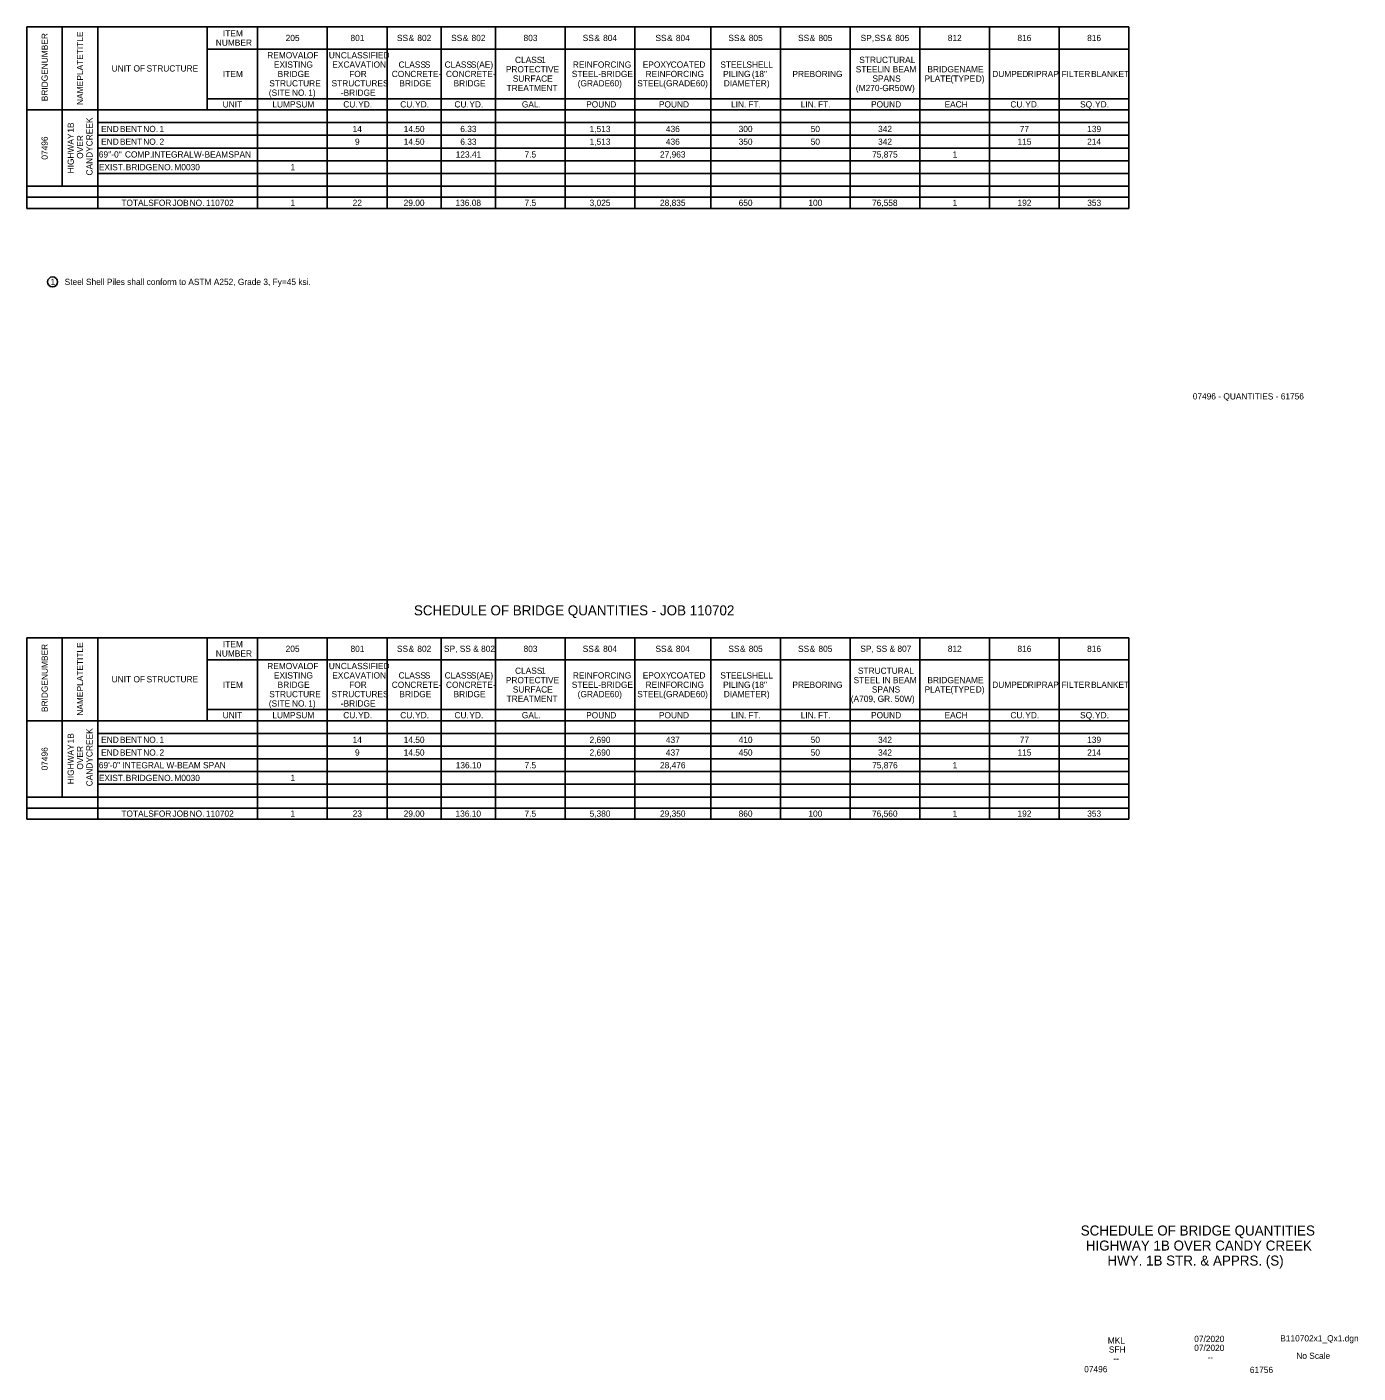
# Model space of a CAD drawing. Extents: x 305.5 to 332.2, y 135.6 to 162.6.
import ezdxf

# ---------------------------------------------------------------- set-up
doc = ezdxf.new("R2010")
doc.units = 0
for name, color, linetype in [('B_Concrete Pattern', 7, 'Continuous'), ('B_Copy In', 7, 'Continuous'), ('B_Dimensions', 7, 'Continuous'), ('B_Text', 7, 'Continuous'), ('B_Title Text', 7, 'Continuous')]:
    doc.layers.add(name, color=color, linetype=linetype)

msp = doc.modelspace()

# ---------------------------------------------------------------- linework, layer by layer
at = {"layer": 'B_Concrete Pattern'}
for p, q in [((305.498, 162.601), (305.498, 162.601)), ((305.498, 150.365), (305.498, 150.365))]:
    msp.add_line(p, q, dxfattribs=at)
at = {"layer": 'B_Dimensions'}
msp.add_circle((306.012, 157.493), 0.1, dxfattribs=at)
at = {"layer": 'B_Text'}
for p, q in [((305.498, 162.601), (327.569, 162.601)), ((305.498, 158.966), (305.498, 162.601)), ((306.207, 159.41), (306.207, 162.601)), ((306.916, 158.966), (306.916, 162.601)), ((309.11, 160.939), (309.11, 162.601)), ((310.118, 158.966), (310.118, 162.601)), ((311.514, 158.966), (311.514, 162.601)), ((312.711, 158.966), (312.711, 162.601)), ((313.797, 158.966), (313.797, 162.601)), ((314.883, 158.966), (314.883, 162.601)), ((316.279, 158.966), (316.279, 162.601)), ((317.675, 158.966), (317.675, 162.601)), ((319.193, 158.966), (319.193, 162.601)), ((320.589, 158.966), (320.589, 162.601)), ((321.985, 158.966), (321.985, 162.601)), ((323.381, 158.966), (323.381, 162.601)), ((324.777, 158.966), (324.777, 162.601)), ((326.173, 158.966), (326.173, 162.601)), ((327.569, 158.966), (327.569, 162.601)), ((309.11, 162.157), (327.569, 162.157)), ((309.11, 161.16), (327.569, 161.16)), ((305.498, 160.939), (327.569, 160.939)), ((306.916, 160.684), (327.569, 160.684)), ((306.916, 160.429), (327.569, 160.429)), ((306.916, 160.174), (327.569, 160.174)), ((306.916, 159.919), (327.569, 159.919)), ((306.916, 159.664), (327.569, 159.664)), ((305.498, 159.41), (327.569, 159.41)), ((305.498, 159.188), (327.569, 159.188)), ((305.498, 158.966), (327.569, 158.966)), ((305.498, 150.365), (327.569, 150.365)), ((305.498, 146.731), (305.498, 150.365)), ((306.207, 147.174), (306.207, 150.365)), ((306.916, 146.731), (306.916, 150.365)), ((309.11, 148.703), (309.11, 150.365)), ((310.118, 146.731), (310.118, 150.365)), ((311.514, 146.731), (311.514, 150.365)), ((312.711, 146.731), (312.711, 150.365)), ((313.797, 146.731), (313.797, 150.365)), ((314.883, 146.731), (314.883, 150.365)), ((316.279, 146.731), (316.279, 150.365)), ((317.675, 146.731), (317.675, 150.365)), ((319.193, 146.731), (319.193, 150.365)), ((320.589, 146.731), (320.589, 150.365)), ((321.985, 146.731), (321.985, 150.365)), ((323.381, 146.731), (323.381, 150.365)), ((324.777, 146.731), (324.777, 150.365)), ((326.173, 146.731), (326.173, 150.365)), ((327.569, 146.731), (327.569, 150.365)), ((309.11, 149.922), (327.569, 149.922)), ((309.11, 148.925), (327.569, 148.925)), ((305.498, 148.703), (327.569, 148.703)), ((306.916, 148.448), (327.569, 148.448)), ((306.916, 148.193), (327.569, 148.193)), ((306.916, 147.938), (327.569, 147.938)), ((306.916, 147.684), (327.569, 147.684)), ((306.916, 147.429), (327.569, 147.429)), ((305.498, 147.174), (327.569, 147.174)), ((305.498, 146.952), (327.569, 146.952)), ((305.498, 146.731), (327.569, 146.731))]:
    msp.add_line(p, q, dxfattribs=at)

# ---------------------------------------------------------------- texts
at = {"layer": 'B_Copy In'}
for s, height, p in [('07496 - QUANTITIES - 61756', 0.1248, (328.849, 155.138)), ('SCHEDULE OF BRIDGE QUANTITIES', 0.2004, (326.605, 138.39)), ('HIGHWAY 1B OVER CANDY CREEK', 0.2004, (326.707, 138.089)), ('HWY. 1B STR. & APPRS. (S)', 0.2004, (327.14, 137.788)), ('MKL', 0.1248, (327.147, 136.225)), ('07/2020', 0.1248, (328.878, 136.257)), ('07/2020', 0.1248, (328.878, 136.077)), ('B110702x1_Qx1.dgn', 0.1248, (330.602, 136.268)), ('SFH', 0.1248, (327.169, 136.045)), ('--', 0.1248, (327.258, 135.865)), ('--', 0.1248, (329.145, 135.89)), ('No Scale', 0.1248, (330.923, 135.919)), ('07496', 0.125, (326.674, 135.65)), ('61756', 0.125, (329.992, 135.636))]:
    msp.add_text(s, height=height, dxfattribs=at).set_placement(p)
at = {"layer": 'B_Text'}
for s, p in [(' NUMBER', (305.915, 161.706)), (' TITLE', (306.624, 162.007)), (' PLATE', (306.624, 161.479)), ('BRIDGE', (305.915, 161.112)), ('NAME', (306.624, 161.037)), (' CREEK', (306.812, 160.163)), ('HIGHWAY', (306.437, 159.667)), (' 1B', (306.437, 160.436)), ('07496', (305.915, 159.942)), ('OVER', (306.624, 159.959)), ('CANDY', (306.812, 159.625)), (' NUMBER', (305.915, 149.471)), (' TITLE', (306.624, 149.771)), (' PLATE', (306.624, 149.243)), ('BRIDGE', (305.915, 148.876)), ('NAME', (306.624, 148.802)), (' 1B', (306.437, 148.201)), (' CREEK', (306.812, 147.927)), ('07496', (305.915, 147.707)), ('HIGHWAY', (306.437, 147.431)), ('OVER', (306.624, 147.723)), ('CANDY', (306.812, 147.389))]:
    msp.add_text(s, height=0.125, rotation=90, dxfattribs=at).set_placement(p)
for s, height, p in [('NUMBER', 0.125, (309.281, 162.223)), ('ITEM', 0.125, (309.424, 162.41)), ('205', 0.125, (310.68, 162.317)), ('801', 0.125, (311.979, 162.317)), ('SS', 0.125, (312.909, 162.317)), (' &', 0.125, (313.096, 162.317)), (' 802', 0.125, (313.271, 162.317)), ('SS', 0.125, (313.995, 162.317)), (' &', 0.125, (314.182, 162.317)), (' 802', 0.125, (314.357, 162.317)), ('803', 0.125, (315.445, 162.317)), ('SS', 0.125, (316.63, 162.317)), (' &', 0.125, (316.817, 162.317)), (' 804', 0.125, (316.992, 162.317)), ('SS', 0.125, (318.087, 162.317)), (' &', 0.125, (318.274, 162.317)), (' 804', 0.125, (318.449, 162.317)), ('SS', 0.125, (319.547, 162.317)), (' &', 0.125, (319.734, 162.317)), (' 805', 0.125, (319.909, 162.317)), ('SS', 0.125, (320.943, 162.317)), (' &', 0.125, (321.13, 162.317)), (' 805', 0.125, (321.305, 162.317)), ('SP,', 0.125, (322.196, 162.317)), (' SS', 0.125, (322.428, 162.317)), (' &', 0.125, (322.669, 162.317)), (' 805', 0.125, (322.844, 162.317)), ('812', 0.125, (323.942, 162.317)), ('816', 0.125, (325.337, 162.317)), ('816', 0.125, (326.733, 162.317)), ('REMOVAL', 0.125, (310.311, 161.971)), (' OF', 0.125, (311.059, 161.971)), ('UNCLASSIFIED', 0.125, (311.544, 161.971)), ('UNIT', 0.125, (307.194, 161.707)), (' OF', 0.125, (307.586, 161.707)), (' STRUCTURE', 0.125, (307.849, 161.707)), ('EXISTING', 0.125, (310.445, 161.784)), ('EXCAVATION', 0.125, (311.614, 161.784)), ('CLASS', 0.125, (312.942, 161.784)), (' S', 0.125, (313.421, 161.784)), ('CLASS', 0.125, (313.864, 161.784)), (' S(AE)', 0.125, (314.343, 161.784)), ('PROTECTIVE', 0.125, (315.09, 161.69)), ('CLASS', 0.125, (315.274, 161.878)), (' 1', 0.125, (315.753, 161.878)), ('REINFORCING', 0.125, (316.432, 161.784)), ('EPOXY', 0.125, (317.832, 161.784)), (' COATED', 0.125, (318.345, 161.784)), ('STEEL', 0.125, (319.387, 161.784)), (' SHELL', 0.125, (319.862, 161.784)), ('STEEL', 0.125, (322.099, 161.69)), ('STRUCTURAL', 0.125, (322.169, 161.878)), (' IN', 0.125, (322.573, 161.69)), (' BEAM', 0.125, (322.793, 161.69)), ('BRIDGE', 0.125, (323.534, 161.69)), (' NAME', 0.125, (324.129, 161.69)), ('ITEM', 0.125, (309.424, 161.596)), ('STRUCTURE', 0.125, (310.352, 161.409)), ('BRIDGE', 0.125, (310.519, 161.596)), ('STRUCTURES', 0.125, (311.599, 161.409)), ('FOR', 0.125, (311.952, 161.596)), ('CONCRETE-', 0.125, (312.805, 161.596)), ('BRIDGE', 0.125, (312.957, 161.409)), ('CONCRETE-', 0.125, (313.891, 161.596)), ('BRIDGE', 0.125, (314.043, 161.409)), ('SURFACE', 0.125, (315.23, 161.503)), ('STEEL-BRIDGE', 0.125, (316.411, 161.596)), ('(GRADE', 0.125, (316.529, 161.409)), (' 60)', 0.125, (317.127, 161.409)), ('STEEL', 0.125, (317.722, 161.409)), ('REINFORCING', 0.125, (317.889, 161.596)), (' (GRADE', 0.125, (318.196, 161.409)), (' 60)', 0.125, (318.848, 161.409)), ('PILING', 0.125, (319.442, 161.596)), ('DIAMETER)', 0.125, (319.454, 161.409)), (' (18"', 0.125, (319.972, 161.596)), ('PREBORING', 0.125, (320.83, 161.596)), ('SPANS', 0.125, (322.433, 161.503)), ('PLATE', 0.125, (323.476, 161.503)), (' (TYPE', 0.125, (323.95, 161.503)), (' D)', 0.125, (324.455, 161.503)), ('DUMPED', 0.125, (324.832, 161.596)), (' RIPRAP', 0.125, (325.497, 161.596)), ('FILTER', 0.125, (326.22, 161.596)), (' BLANKET', 0.125, (326.766, 161.596)), ('(SITE', 0.125, (310.343, 161.221)), (' NO.', 0.125, (310.76, 161.221)), (' 1)', 0.125, (311.086, 161.221)), ('-BRIDGE', 0.125, (311.784, 161.221)), ('TREATMENT', 0.125, (315.105, 161.315)), ('(M270-GR50W)', 0.125, (322.101, 161.315)), ('UNIT', 0.125, (309.418, 160.987)), ('LUMP', 0.125, (310.414, 160.987)), (' SUM', 0.125, (310.837, 160.987)), ('CU.', 0.125, (311.834, 160.987)), (' YD.', 0.125, (312.086, 160.987)), ('CU.', 0.125, (312.975, 160.987)), (' YD.', 0.125, (313.227, 160.987)), ('CU.', 0.125, (314.061, 160.987)), (' YD.', 0.125, (314.313, 160.987)), ('GAL.', 0.125, (315.411, 160.987)), ('POUND', 0.125, (316.699, 160.987)), ('POUND', 0.125, (318.156, 160.987)), ('LIN.', 0.125, (319.601, 160.987)), (' FT.', 0.125, (319.901, 160.987)), ('LIN.', 0.125, (320.997, 160.987)), (' FT.', 0.125, (321.297, 160.987)), ('POUND', 0.125, (322.405, 160.987)), ('EACH', 0.125, (323.876, 160.987)), ('CU.', 0.125, (325.196, 160.987)), (' YD.', 0.125, (325.448, 160.987)), ('SQ.', 0.125, (326.592, 160.987)), (' YD.', 0.125, (326.845, 160.987)), (' END', 0.125, (306.938, 160.494)), (' BENT', 0.125, (307.314, 160.494)), (' NO.', 0.125, (307.781, 160.494)), (' 1', 0.125, (308.107, 160.494)), ('14', 0.125, (312.021, 160.494)), ('14.50', 0.125, (313.044, 160.494)), ('6.33', 0.125, (314.178, 160.494)), ('1,513', 0.125, (316.768, 160.494)), ('436', 0.125, (318.296, 160.494)), ('300', 0.125, (319.753, 160.494)), ('50', 0.125, (321.196, 160.494)), ('342', 0.125, (322.546, 160.494)), ('77', 0.125, (325.384, 160.494)), ('139', 0.125, (326.734, 160.494)), (' END', 0.125, (306.938, 160.239)), (' BENT', 0.125, (307.314, 160.239)), (' NO.', 0.125, (307.781, 160.239)), (' 2', 0.125, (308.107, 160.239)), ('9', 0.125, (312.069, 160.239)), ('14.50', 0.125, (313.044, 160.239)), ('6.33', 0.125, (314.178, 160.239)), ('1,513', 0.125, (316.768, 160.239)), ('436', 0.125, (318.296, 160.239)), ('350', 0.125, (319.753, 160.239)), ('50', 0.125, (321.196, 160.239)), ('342', 0.125, (322.546, 160.239)), ('115', 0.125, (325.339, 160.239)), ('214', 0.125, (326.733, 160.239)), ('69\'\'-0"', 0.125, (306.938, 159.984)), (' COMP.', 0.125, (307.414, 159.984)), (' INTEGRAL', 0.125, (307.956, 159.984)), (' W-BEAM', 0.125, (308.795, 159.984)), (' SPAN', 0.125, (309.487, 159.984)), ('123.41', 0.125, (314.086, 159.984)), ('7.5', 0.125, (315.465, 159.984)), ('27,963', 0.125, (318.178, 159.984)), ('75,875', 0.125, (322.427, 159.984)), ('1', 0.125, (324.039, 159.984)), ('EXIST.', 0.125, (306.938, 159.729)), (' BRIDGE', 0.125, (307.431, 159.729)), (' NO.', 0.125, (308.079, 159.729)), (' M0030', 0.125, (308.405, 159.729)), ('1', 0.125, (310.776, 159.729)), ('TOTALS', 0.125, (307.389, 159.015)), (' FOR', 0.125, (307.992, 159.015)), (' JOB', 0.125, (308.366, 159.015)), (' NO.', 0.125, (308.71, 159.015)), (' 110702', 0.125, (309.036, 159.015)), ('1', 0.125, (310.776, 159.015)), ('22', 0.125, (312.023, 159.015)), ('29.00', 0.125, (313.044, 159.015)), ('136.08', 0.125, (314.082, 159.015)), ('7.5', 0.125, (315.465, 159.015)), ('3,025', 0.125, (316.768, 159.015)), ('28,835', 0.125, (318.178, 159.015)), ('650', 0.125, (319.753, 159.015)), ('100', 0.125, (321.15, 159.015)), ('76,558', 0.125, (322.425, 159.015)), ('1', 0.125, (324.039, 159.015)), ('192', 0.125, (325.338, 159.015)), ('353', 0.125, (326.735, 159.015)), ('1', 0.125, (305.973, 157.431)), ('Steel Shell Piles shall conform to ASTM A252, Grade 3, Fy=45 ksi.', 0.1248, (306.254, 157.431)), ('ITEM', 0.125, (309.424, 150.175)), ('205', 0.125, (310.68, 150.081)), ('801', 0.125, (311.979, 150.081)), ('SS', 0.125, (312.909, 150.081)), (' &', 0.125, (313.096, 150.081)), (' 802', 0.125, (313.271, 150.081)), ('SP, SS & 802', 0.125, (313.851, 150.082)), ('803', 0.125, (315.445, 150.081)), ('SS', 0.125, (316.63, 150.081)), (' &', 0.125, (316.817, 150.081)), (' 804', 0.125, (316.992, 150.081)), ('SS', 0.125, (318.087, 150.081)), (' &', 0.125, (318.274, 150.081)), (' 804', 0.125, (318.449, 150.081)), ('SS', 0.125, (319.547, 150.081)), (' &', 0.125, (319.734, 150.081)), (' 805', 0.125, (319.909, 150.081)), ('SS', 0.125, (320.943, 150.081)), (' &', 0.125, (321.13, 150.081)), (' 805', 0.125, (321.305, 150.081)), ('SP, SS & 807', 0.125, (322.19, 150.082)), ('812', 0.125, (323.942, 150.081)), ('816', 0.125, (325.337, 150.081)), ('816', 0.125, (326.733, 150.081)), ('NUMBER', 0.125, (309.281, 149.987)), ('REMOVAL', 0.125, (310.311, 149.736)), ('EXISTING', 0.125, (310.445, 149.548)), (' OF', 0.125, (311.059, 149.736)), ('UNCLASSIFIED', 0.125, (311.544, 149.736)), ('EXCAVATION', 0.125, (311.614, 149.548)), ('CLASS', 0.125, (312.942, 149.548)), (' S', 0.125, (313.421, 149.548)), ('CLASS', 0.125, (313.864, 149.548)), (' S(AE)', 0.125, (314.343, 149.548)), ('CLASS', 0.125, (315.274, 149.642)), (' 1', 0.125, (315.753, 149.642)), ('REINFORCING', 0.125, (316.432, 149.548)), ('EPOXY', 0.125, (317.832, 149.548)), (' COATED', 0.125, (318.345, 149.548)), ('STEEL', 0.125, (319.387, 149.548)), (' SHELL', 0.125, (319.862, 149.548)), ('STRUCTURAL', 0.1248, (322.142, 149.642)), ('UNIT', 0.125, (307.194, 149.471)), (' OF', 0.125, (307.586, 149.471)), (' STRUCTURE', 0.125, (307.849, 149.471)), ('ITEM', 0.125, (309.424, 149.361)), ('BRIDGE', 0.125, (310.519, 149.361)), ('FOR', 0.125, (311.952, 149.361)), ('CONCRETE-', 0.125, (312.805, 149.361)), ('CONCRETE-', 0.125, (313.891, 149.361)), ('PROTECTIVE', 0.125, (315.09, 149.454)), ('SURFACE', 0.125, (315.23, 149.267)), ('STEEL-BRIDGE', 0.125, (316.411, 149.361)), ('REINFORCING', 0.125, (317.889, 149.361)), ('PILING', 0.125, (319.442, 149.361)), (' (18"', 0.125, (319.972, 149.361)), ('PREBORING', 0.125, (320.83, 149.361)), ('STEEL IN BEAM', 0.1248, (322.056, 149.454)), ('SPANS', 0.1248, (322.421, 149.267)), ('BRIDGE', 0.125, (323.534, 149.454)), (' (TYPE', 0.125, (323.95, 149.267)), (' NAME', 0.125, (324.129, 149.454)), (' D)', 0.125, (324.455, 149.267)), ('DUMPED', 0.125, (324.832, 149.361)), (' RIPRAP', 0.125, (325.497, 149.361)), ('FILTER', 0.125, (326.22, 149.361)), (' BLANKET', 0.125, (326.766, 149.361)), ('STRUCTURE', 0.125, (310.352, 149.173)), ('STRUCTURES', 0.125, (311.599, 149.173)), ('BRIDGE', 0.125, (312.957, 149.173)), ('BRIDGE', 0.125, (314.043, 149.173)), ('TREATMENT', 0.125, (315.105, 149.079)), ('(GRADE', 0.125, (316.529, 149.173)), (' 60)', 0.125, (317.127, 149.173)), ('STEEL', 0.125, (317.722, 149.173)), (' (GRADE', 0.125, (318.196, 149.173)), (' 60)', 0.125, (318.848, 149.173)), ('DIAMETER)', 0.125, (319.454, 149.173)), ('(A709, GR. 50W)', 0.1248, (321.999, 149.08)), ('PLATE', 0.125, (323.476, 149.267)), ('UNIT', 0.125, (309.418, 148.751)), ('(SITE', 0.125, (310.343, 148.986)), ('LUMP', 0.125, (310.414, 148.751)), (' NO.', 0.125, (310.76, 148.986)), (' SUM', 0.125, (310.837, 148.751)), (' 1)', 0.125, (311.086, 148.986)), ('-BRIDGE', 0.125, (311.784, 148.986)), ('CU.', 0.125, (311.834, 148.751)), (' YD.', 0.125, (312.086, 148.751)), ('CU.', 0.125, (312.975, 148.751)), (' YD.', 0.125, (313.227, 148.751)), ('CU.', 0.125, (314.061, 148.751)), (' YD.', 0.125, (314.313, 148.751)), ('GAL.', 0.125, (315.411, 148.751)), ('POUND', 0.125, (316.699, 148.751)), ('POUND', 0.125, (318.156, 148.751)), ('LIN.', 0.125, (319.601, 148.751)), (' FT.', 0.125, (319.901, 148.751)), ('LIN.', 0.125, (320.997, 148.751)), (' FT.', 0.125, (321.297, 148.751)), ('POUND', 0.125, (322.405, 148.751)), ('EACH', 0.125, (323.876, 148.751)), ('CU.', 0.125, (325.196, 148.751)), (' YD.', 0.125, (325.448, 148.751)), ('SQ.', 0.125, (326.592, 148.751)), (' YD.', 0.125, (326.845, 148.751)), (' END', 0.125, (306.938, 148.258)), (' BENT', 0.125, (307.314, 148.258)), (' NO.', 0.125, (307.781, 148.258)), (' 1', 0.125, (308.107, 148.258)), ('14', 0.125, (312.021, 148.258)), ('14.50', 0.125, (313.044, 148.258)), ('2,690', 0.125, (316.768, 148.258)), ('437', 0.125, (318.296, 148.258)), ('410', 0.125, (319.753, 148.258)), ('50', 0.125, (321.196, 148.258)), ('342', 0.125, (322.546, 148.258)), ('77', 0.125, (325.384, 148.258)), ('139', 0.125, (326.734, 148.258)), (' END', 0.125, (306.938, 148.003)), (' BENT', 0.125, (307.314, 148.003)), (' NO.', 0.125, (307.781, 148.003)), (' 2', 0.125, (308.107, 148.003)), ('9', 0.125, (312.069, 148.003)), ('14.50', 0.125, (313.044, 148.003)), ('2,690', 0.125, (316.768, 148.003)), ('437', 0.125, (318.296, 148.003)), ('450', 0.125, (319.753, 148.003)), ('50', 0.125, (321.196, 148.003)), ('342', 0.125, (322.546, 148.003)), ('115', 0.125, (325.339, 148.003)), ('214', 0.125, (326.733, 148.003)), ('69\'-0" INTEGRAL W-BEAM SPAN', 0.125, (306.938, 147.749)), ('136.10', 0.125, (314.086, 147.748)), ('7.5', 0.125, (315.465, 147.748)), ('28,476', 0.125, (318.178, 147.748)), ('75,876', 0.125, (322.427, 147.748)), ('1', 0.125, (324.039, 147.748)), ('EXIST.', 0.125, (306.938, 147.494)), (' BRIDGE', 0.125, (307.431, 147.494)), (' NO.', 0.125, (308.079, 147.494)), (' M0030', 0.125, (308.405, 147.494)), ('1', 0.125, (310.776, 147.494)), ('TOTALS', 0.125, (307.389, 146.779)), (' FOR', 0.125, (307.992, 146.779)), (' JOB', 0.125, (308.366, 146.779)), (' NO.', 0.125, (308.71, 146.779)), (' 110702', 0.125, (309.036, 146.779)), ('1', 0.125, (310.776, 146.779)), ('23', 0.125, (312.023, 146.779)), ('29.00', 0.125, (313.044, 146.779)), ('136.10', 0.125, (314.082, 146.779)), ('7.5', 0.125, (315.465, 146.779)), ('5,380', 0.125, (316.768, 146.779)), ('29,350', 0.125, (318.178, 146.779)), ('860', 0.125, (319.753, 146.779)), ('100', 0.125, (321.15, 146.779)), ('76,560', 0.125, (322.425, 146.779)), ('1', 0.125, (324.039, 146.779)), ('192', 0.125, (325.338, 146.779)), ('353', 0.125, (326.735, 146.779))]:
    msp.add_text(s, height=height, dxfattribs=at).set_placement(p)
at = {"layer": 'B_Title Text'}
msp.add_text('SCHEDULE OF BRIDGE QUANTITIES - JOB 110702', height=0.2004, dxfattribs=at).set_placement((313.249, 150.813))

doc.saveas('drawing.dxf')
